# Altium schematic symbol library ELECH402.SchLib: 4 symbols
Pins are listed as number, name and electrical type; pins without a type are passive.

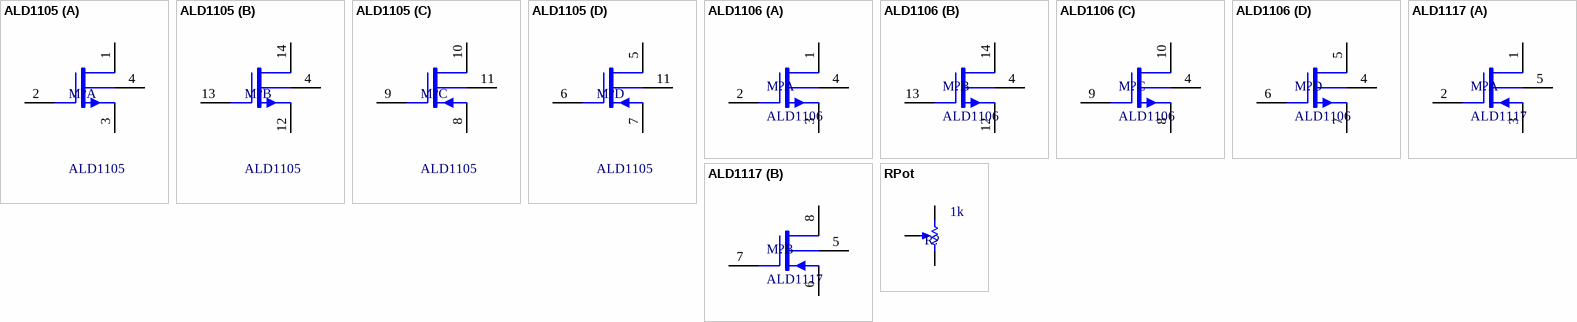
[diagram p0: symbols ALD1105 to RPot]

## ALD1105
designator M?
Dual P-channel and dual N-channel matched MOSFET array
footprint DIP-14 (DIP, 14-Pin, Row Spacing 7.62 mm, Pitch 2.54 mm)
part A pins: 1 DN1, 2 GN1, 3 SN1, 4 V-
part B pins: 4 V-, 12 SN2, 13 GN2, 14 DN2
part C pins: 8 SP2, 9 GP2, 10 DP2, 11 V+
part D pins: 5 DP1, 6 GP1, 7 SP1, 11 V+

## ALD1106
designator M?
Quad N-channel matched MOSFET array
footprint DIP-14 (DIP, 14-Pin, Row Spacing 7.62 mm, Pitch 2.54 mm)
part A pins: 1 DN1, 2 GN1, 3 SN1, 4 V-
part B pins: 4 V-, 12 SN2, 13 GN2, 14 DN2
part C pins: 4 V-, 8 SN3, 9 GN3, 10 DN3
part D pins: 4 V-, 5 DN4, 6 GN4, 7 SN4

## ALD1117
designator M?
Dual P-channel matched MOSFET array
footprint DIP-8 (DIP, 8-Pin, Row Spacing 7.62 mm, Pitch 2.54 mm)
part A pins: 1 DP1, 2 GP1, 3 SP1, 5 V+
part B pins: 5 V+, 6 SP2, 7 GP2, 8 DP2

## RPot
designator R?  value 1k
Potentiometer; Sim Note: Enter the Resistance value and the set point into parameter fields.; Set Position: 0.5
footprint VR5 (Thru-Hole; 3 Leads)
simulation model POT (Potentiometer)
pins: 1 TOP, 2 TAP, 3 BOT
1 alternate drawing of the same symbol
